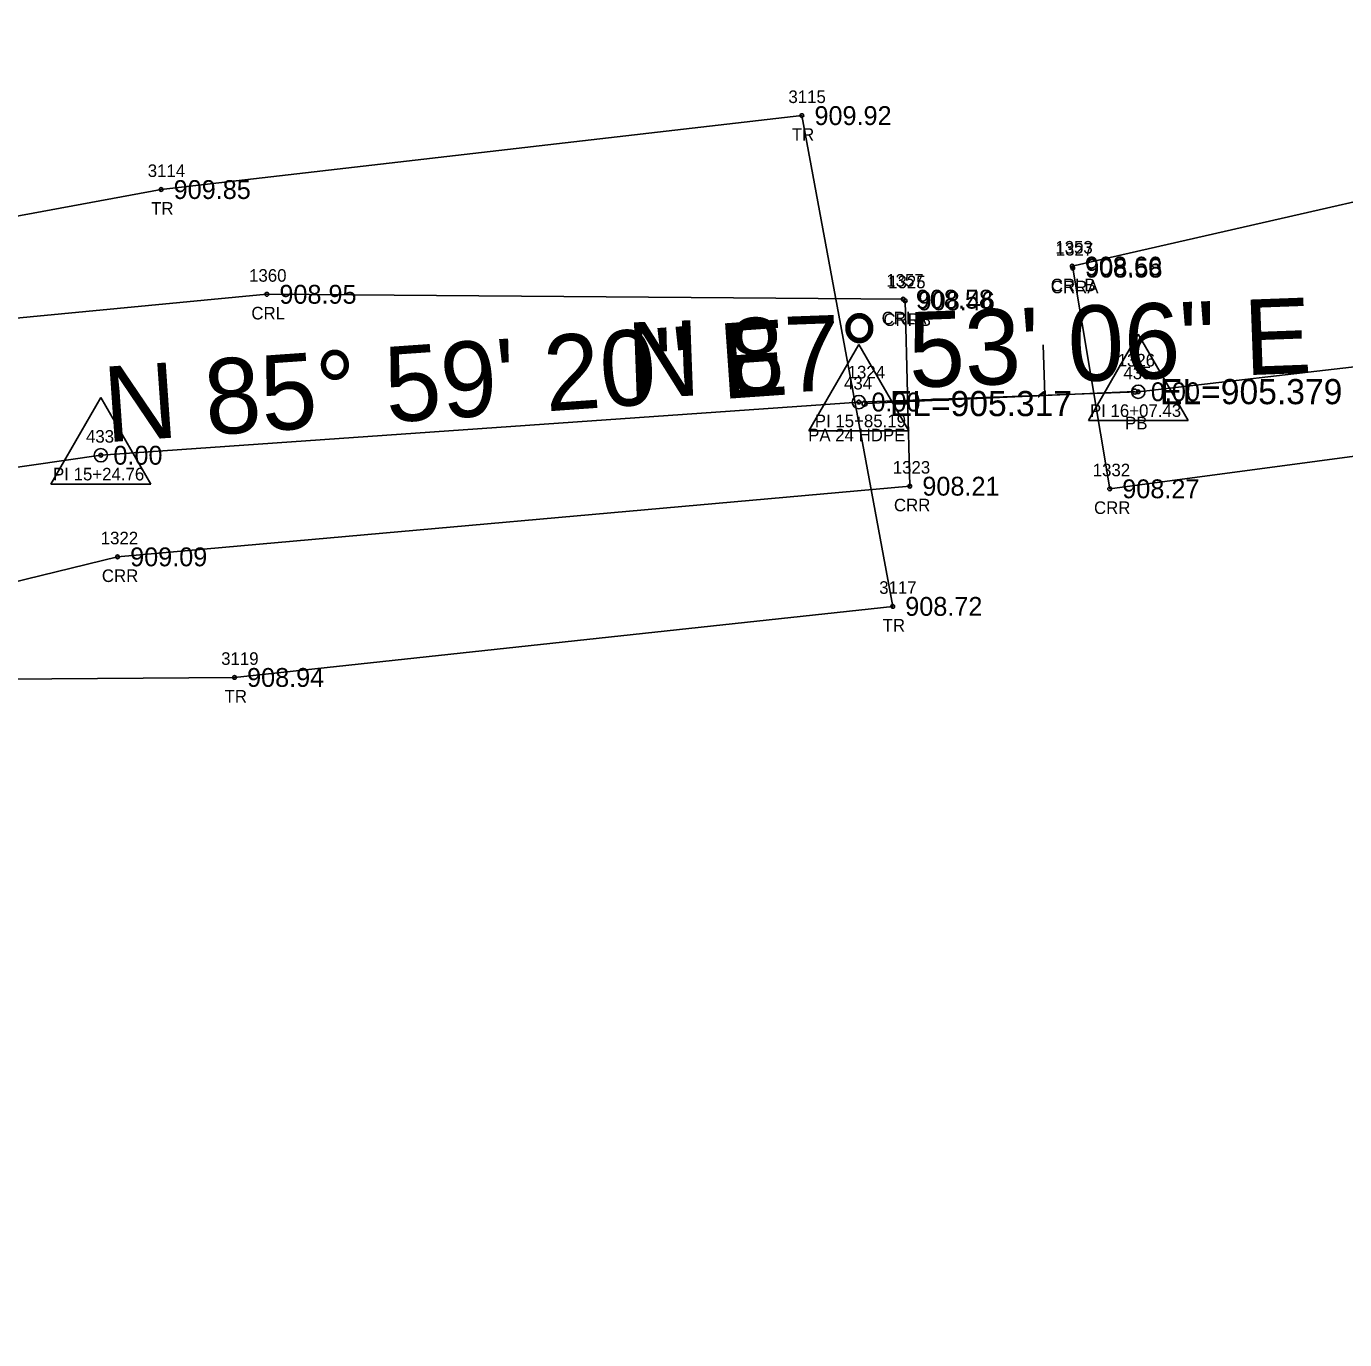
# Model space of a CAD drawing. Extents: x 1528109 to 1531398, y 1157799 to 1162548.
# Drawn here: x 1529869.1 to 1529973.9, y 1159860.9 to 1159965.4 of the extents above; entities that cross this region are included whole.
import ezdxf

# ---------------------------------------------------------------- set-up
doc = ezdxf.new("R2010")
doc.units = 0
for name, color, linetype in [('RD_EX_DR_Pipe', 7, 'Continuous'), ('RD_EX_DR_Pipe_txCode', 7, 'Continuous'), ('RD_EX_H2O', 7, 'Continuous'), ('RD_EX_H2O_txCode', 7, 'Continuous'), ('RD_EX_TX_H2O_ELEV', 7, 'Continuous'), ('RD_EX_TX_VEG_ELEV', 7, 'Continuous'), ('RD_EX_VEG', 7, 'Continuous'), ('RD_EX_VEG_txCode', 7, 'Continuous'), ('RD_HC_Cl', 7, 'Continuous'), ('RD_HC_Data', 7, 'Continuous'), ('RD_HC_Data_Tic', 7, 'Continuous'), ('RD_HC_Survey_ELEV', 7, 'Continuous'), ('RD_HC_txCode', 7, 'Continuous'), ('RD_SMD_Locator', 7, 'Continuous'), ('RD_TX_Pipe_ElevEX', 7, 'Continuous')]:
    doc.layers.add(name, color=color, linetype=linetype)

msp = doc.modelspace()

# ---------------------------------------------------------------- linework, layer by layer
at = {"layer": 'RD_EX_DR_Pipe'}
msp.add_line((1529935.76, 1159935.38), (1529957.25, 1159936.33), dxfattribs=at)
at = {"layer": 'RD_EX_H2O'}
for points in [[(1530159.12, 1159964.68), (1530129.46, 1159963.01), (1530101.33, 1159965.38), (1530051.55, 1159956.75), (1529995.51, 1159956.17), (1529952.27, 1159946.31)], [(1529952.31, 1159946.15), (1529955.25, 1159928.6), (1530004.73, 1159935.19), (1530051.35, 1159934.34), (1530115.73, 1159939.93), (1530160.76, 1159944.25)], [(1529938.83, 1159943.68), (1529888.22, 1159944.07), (1529845.58, 1159939.99), (1529795.79, 1159930.1), (1529781.58, 1159930.74), (1529751.82, 1159922.01), (1529751.82, 1159922.01), (1529752.28, 1159909.9), (1529735.15, 1159902.1), (1529711.19, 1159893.34), (1529649.14, 1159875.01), (1529611.79, 1159867.22), (1529569.01, 1159857.16), (1529529.3, 1159848.12), (1529463.64, 1159832.32), (1529419.51, 1159820.53), (1529366.55, 1159808.3)], [(1529761.66, 1159891.83), (1529792.97, 1159900.84), (1529809.45, 1159907.17), (1529847.06, 1159916.03), (1529876.35, 1159923.19), (1529939.35, 1159928.81), (1529938.98, 1159943.55)]]:
    msp.add_lwpolyline(points, dxfattribs=at)
at = {"layer": 'RD_EX_VEG'}
msp.add_lwpolyline([(1529811.1, 1159939.7), (1529879.81, 1159952.4), (1529930.77, 1159958.28), (1529937.99, 1159919.25), (1529885.65, 1159913.6), (1529842.08, 1159913.27), (1529802.83, 1159902.31)], dxfattribs=at)
at = {"layer": 'RD_HC_Cl'}
for p, q in [((1529957.52, 1159936.32), (1530051.27, 1159947.11)), ((1529935.3, 1159935.5), (1529957.52, 1159936.32)), ((1529875.02, 1159931.27), (1529935.3, 1159935.5)), ((1529805.85, 1159921.39), (1529875.02, 1159931.27))]:
    msp.add_line(p, q, dxfattribs=at)
at = {"layer": 'RD_HC_Data'}
for p, q in [((1529931.33, 1159933.2), (1529935.3, 1159940.08)), ((1529935.3, 1159940.08), (1529939.27, 1159933.2)), ((1529953.55, 1159934.03), (1529957.52, 1159940.9)), ((1529957.52, 1159940.9), (1529961.49, 1159934.03)), ((1529871.05, 1159928.98), (1529875.02, 1159935.86)), ((1529875.02, 1159935.86), (1529878.99, 1159928.98)), ((1529953.55, 1159934.03), (1529961.49, 1159934.03)), ((1529931.33, 1159933.2), (1529939.27, 1159933.2)), ((1529871.05, 1159928.98), (1529878.99, 1159928.98))]:
    msp.add_line(p, q, dxfattribs=at)
for centre in [(1529957.52, 1159936.32), (1529935.3, 1159935.5), (1529875.02, 1159931.27)]:
    msp.add_circle(centre, 0.529, dxfattribs=at)
at = {"layer": 'RD_HC_Data_Tic'}
msp.add_line((1529950.1, 1159936.04), (1529949.95, 1159940.04), dxfattribs=at)
at = {"layer": 'RD_SMD_Locator'}
for centre, radius in [((1529930.77, 1159958.28), 0.15), ((1529879.81, 1159952.4), 0.15), ((1529952.27, 1159946.31), 0.15), ((1529952.31, 1159946.15), 0.15), ((1529888.22, 1159944.07), 0.15), ((1529938.83, 1159943.68), 0.15), ((1529938.98, 1159943.55), 0.15), ((1529957.25, 1159936.33), 0.2), ((1529957.52, 1159936.32), 0.15), ((1529935.3, 1159935.5), 0.15), ((1529935.76, 1159935.38), 0.2), ((1529875.02, 1159931.27), 0.15), ((1529939.35, 1159928.81), 0.15), ((1529955.25, 1159928.6), 0.15), ((1529876.35, 1159923.19), 0.15), ((1529937.99, 1159919.25), 0.15), ((1529885.65, 1159913.6), 0.15)]:
    msp.add_circle(centre, radius, dxfattribs=at)

# ---------------------------------------------------------------- texts
at = {"layer": 'RD_EX_DR_Pipe_txCode'}
for s, p in [('1326', (1529955.88, 1159938.33)), ('1324', (1529934.41, 1159937.38)), ('PB', (1529956.47, 1159933.33)), ('PA 24 HDPE', (1529931.27, 1159932.38))]:
    msp.add_text(s, height=1, dxfattribs=at).set_placement(p)
at = {"layer": 'RD_EX_H2O_txCode'}
for s, p in [('1353', (1529950.92, 1159947.31)), ('1327', (1529950.96, 1159947.15)), ('1360', (1529886.81, 1159945.07)), ('1357', (1529937.48, 1159944.68)), ('1325', (1529937.63, 1159944.55)), ('CRLB', (1529950.56, 1159944.31)), ('CRRA', (1529950.57, 1159944.15)), ('CRL', (1529886.99, 1159942.07)), ('CRLA', (1529937.11, 1159941.68)), ('CRRB', (1529937.25, 1159941.55)), ('1323', (1529938, 1159929.81)), ('1332', (1529953.9, 1159929.6)), ('CRR', (1529938.09, 1159926.81)), ('CRR', (1529954, 1159926.6)), ('1322', (1529875.01, 1159924.19)), ('CRR', (1529875.1, 1159921.19))]:
    msp.add_text(s, height=1, dxfattribs=at).set_placement(p)
at = {"layer": 'RD_EX_TX_H2O_ELEV'}
for s, p in [('908.66', (1529953.27, 1159945.56)), ('908.58', (1529953.31, 1159945.4)), ('908.95', (1529889.22, 1159943.32)), ('908.58', (1529939.83, 1159942.93)), ('908.46', (1529939.98, 1159942.8)), ('908.21', (1529940.35, 1159928.06)), ('908.27', (1529956.25, 1159927.85)), ('909.09', (1529877.35, 1159922.44))]:
    msp.add_text(s, height=1.5, dxfattribs=at).set_placement(p)
at = {"layer": 'RD_EX_TX_VEG_ELEV'}
for s, p in [('909.92', (1529931.77, 1159957.53)), ('909.85', (1529880.81, 1159951.65)), ('908.72', (1529938.99, 1159918.5)), ('908.94', (1529886.65, 1159912.85))]:
    msp.add_text(s, height=1.5, dxfattribs=at).set_placement(p)
at = {"layer": 'RD_EX_VEG_txCode'}
for s, p in [('3115', (1529929.7, 1159959.28)), ('TR', (1529929.97, 1159956.28)), ('3114', (1529878.75, 1159953.4)), ('TR', (1529879.02, 1159950.4)), ('3117', (1529936.92, 1159920.25)), ('TR', (1529937.19, 1159917.25)), ('3119', (1529884.59, 1159914.6)), ('TR', (1529884.86, 1159911.6))]:
    msp.add_text(s, height=1, dxfattribs=at).set_placement(p)
at = {"layer": 'RD_HC_Data'}
for s, rotation, p in [('N 87%%d 53\' 06" E', 2.1151, (1529916.98, 1159935.82)), ('N 85%%d 59\' 20" E', 4.0112, (1529875.47, 1159932.3))]:
    msp.add_text(s, height=6, rotation=rotation, dxfattribs=at).set_placement(p)
at = {"layer": 'RD_HC_Survey_ELEV'}
for p in [(1529958.52, 1159935.57), (1529936.3, 1159934.75), (1529876.02, 1159930.52)]:
    msp.add_text('0.00', height=1.5, dxfattribs=at).set_placement(p)
at = {"layer": 'RD_HC_txCode'}
for s, p in [('435', (1529956.34, 1159937.32)), ('434', (1529934.12, 1159936.5)), ('PI 16+07.43', (1529953.68, 1159934.32)), ('PI 15+85.19', (1529931.8, 1159933.5)), ('433', (1529873.84, 1159932.27)), ('PI 15+24.76', (1529871.22, 1159929.27))]:
    msp.add_text(s, height=1, dxfattribs=at).set_placement(p)
at = {"layer": 'RD_TX_Pipe_ElevEX'}
for s, p in [('EL=905.379', (1529959.25, 1159935.33)), ('EL=905.317', (1529937.76, 1159934.38))]:
    msp.add_text(s, height=2, dxfattribs=at).set_placement(p)

doc.saveas('drawing.dxf')
